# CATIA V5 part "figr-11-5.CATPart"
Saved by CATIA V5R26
Part number: Part4
Bounding box of the stored display mesh (mm): x -40 to 40, y -90 to 150, z -30.056 to 96
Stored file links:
  D:\_Deepak\CATIA\CATIA V5-6R2016_Deepak\Resources\Part files\Partfiles\c11_catia_v5_6r2016_prt\figr-11-5.CATPart
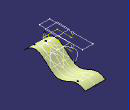
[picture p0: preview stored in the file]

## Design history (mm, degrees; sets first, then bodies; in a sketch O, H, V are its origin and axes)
Body1 (main body)
  Sketch1 on yz-plane, origin (0, 0, 0), H (0, 1, 0), V (0, 0, 1)
    spline S1 through (-90, 0) (-30, 20) (50, -30) (110, -10) (150, -20)
  Extrude1: Element1 Sketch1, Lim1 40, Lim2 40
  Plane1: type Offset, RefPlane xy-plane, Offset 50
  Sketch2 on Plane1, origin (0, 0, 50), H (1, 0, 0), V (0, 1, 0)
    spline S1 through (30, 100) (-10, 40) (20, -10) (-10, -60)
  Plane2: type Offset, RefPlane Plane1, Offset 46
  Sketch3 on Plane2, origin (0, 0, 96), H (1, 0, 0), V (0, 1, 0)
    line L1 (-20, 120) -> (20, 120)
    line L2 (20, 120) -> (20, -50)
    line L3 (20, -50) -> (-20, -50)
    line L4 (-20, -50) -> (-20, 120)
    horizontal: L1 H, L3 H
    vertical: L2 V, L4 V
  MultiSel1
